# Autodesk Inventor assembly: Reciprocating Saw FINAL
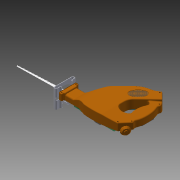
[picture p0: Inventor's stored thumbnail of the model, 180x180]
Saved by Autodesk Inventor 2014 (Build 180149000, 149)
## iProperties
Created: 2008-06
Part Number: Reciprocating Saw FINAL
Document SubType Name: Assembly
Designer: tangg
Mass: 944.675 g
Surface Area: 4194.83 cm^2
Volume: 272.559 cm^3
Density: 3.46595 g/cm^3
Author: tangg
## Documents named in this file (12)
- C:\Users\iTools\Desktop\tutorial files\Dynamic Simulation 1 and 2\Reciprocating Saw FINAL.iam
- C:\Users\iTools\Desktop\tutorial files\Dynamic Simulation 1 and 2\Saw layout.ipt
- C:\Users\iTools\Desktop\tutorial files\Dynamic Simulation 1 and 2\Guide.ipt
- C:\Users\iTools\Desktop\tutorial files\Dynamic Simulation 1 and 2\Motor housing.ipt
- C:\Users\iTools\Desktop\tutorial files\Dynamic Simulation 1 and 2\Case.ipt
- C:\Users\iTools\Desktop\tutorial files\Dynamic Simulation 1 and 2\Follower.ipt
- C:\Users\iTools\Desktop\tutorial files\Dynamic Simulation 1 and 2\Fence.ipt
- C:\Users\iTools\Desktop\tutorial files\Dynamic Simulation 1 and 2\Cam crank.iam
- C:\Users\iTools\Desktop\tutorial files\Dynamic Simulation 1 and 2\Motor.iam
- C:\Users\iTools\Desktop\tutorial files\Dynamic Simulation 1 and 2\Follower Roller.ipt
- C:\Users\iTools\Desktop\tutorial files\Dynamic Simulation 1 and 2\SKFRLS 4 A-2ZANSI.ipt
- C:\Users\iTools\Desktop\tutorial files\Dynamic Simulation 1 and 2\Blade set.iam
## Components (12 placed, 11 different names)
1. Saw layout:1 — Flush:15, Mate:66, Mate:76, Mate:77
2. Case:1 — Flush:16, Mate:74, Flush:19, Flush:20
3. Fence:1 — Flush:16, Mate:74
4. Guide:1 — Flush:15, Mate:71, Mate:72, Mate:88, Mate:89
5. SKF Series RLS- with Two Shields RLS 4 A-2Z:1 — Flush:19
6. SKF Series RLS- with Two Shields RLS 4 A-2Z:2 — Flush:20
7. Motor housing:1 — Mate:66, Mate:73
8. Cam crank:1 [sub-assembly] — Mate:76, Mate:77, Mate:90
9. Motor:1 [sub-assembly] — Mate:73
10. Follower:1 — Mate:71, Mate:72, Mate:75, Flush:17
11. Follower Roller:1 — Mate:75, Flush:17
12. Blade set:1 [sub-assembly] — Mate:88, Mate:89, Mate:90
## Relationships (16: Mate 11, Flush 5)
- Flush:15: Saw layout:1 ↔ Guide:1
- Flush:16: Case:1 ↔ Fence:1
- Mate:66: Saw layout:1 ↔ Motor housing:1
- Mate:71: Guide:1 ↔ Follower:1
- Mate:72: Guide:1 ↔ Follower:1
- Mate:73: Motor housing:1 ↔ Motor:1
- Mate:74: Case:1 ↔ Fence:1
- Mate:75: Follower:1 ↔ Follower Roller:1
- Flush:17: Follower:1 ↔ Follower Roller:1
- Mate:76: Saw layout:1 ↔ Cam crank:1
- Mate:77: Saw layout:1 ↔ Cam crank:1
- Flush:19: Case:1 ↔ SKF Series RLS- with Two Shields RLS 4 A-2Z:1
- Flush:20: Case:1 ↔ SKF Series RLS- with Two Shields RLS 4 A-2Z:2
- Mate:88: Guide:1 ↔ Blade set:1
- Mate:89: Guide:1 ↔ Blade set:1
- Mate:90: Cam crank:1 ↔ Blade set:1
